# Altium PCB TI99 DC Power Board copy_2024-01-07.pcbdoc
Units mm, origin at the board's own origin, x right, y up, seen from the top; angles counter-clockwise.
Board outline 152.53 x 137.41 mm, 2 copper layers (Top Layer, Bottom Layer); 9 components, 10 nets, 53 pads, 1 vias.
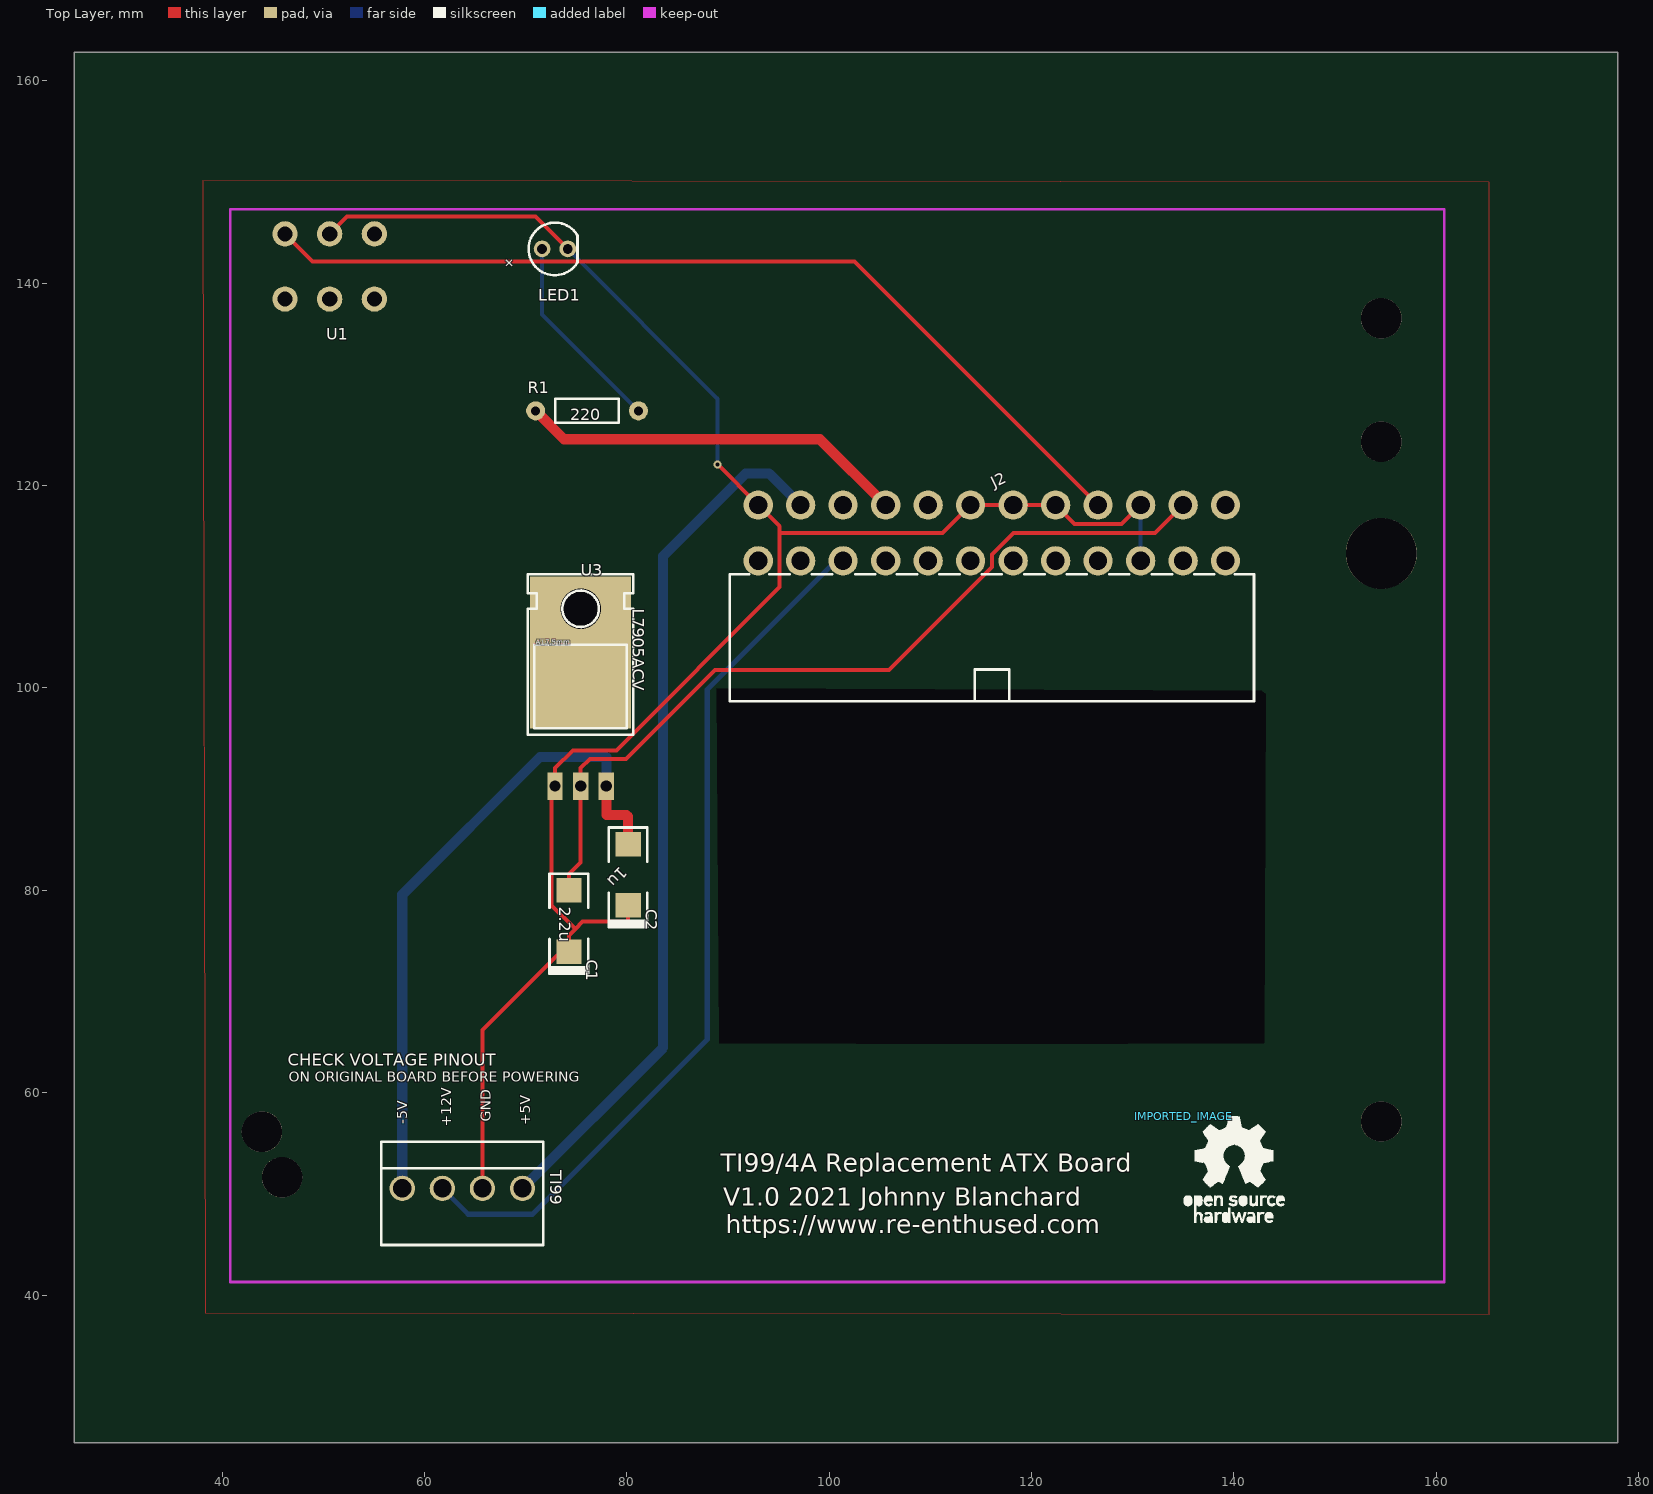
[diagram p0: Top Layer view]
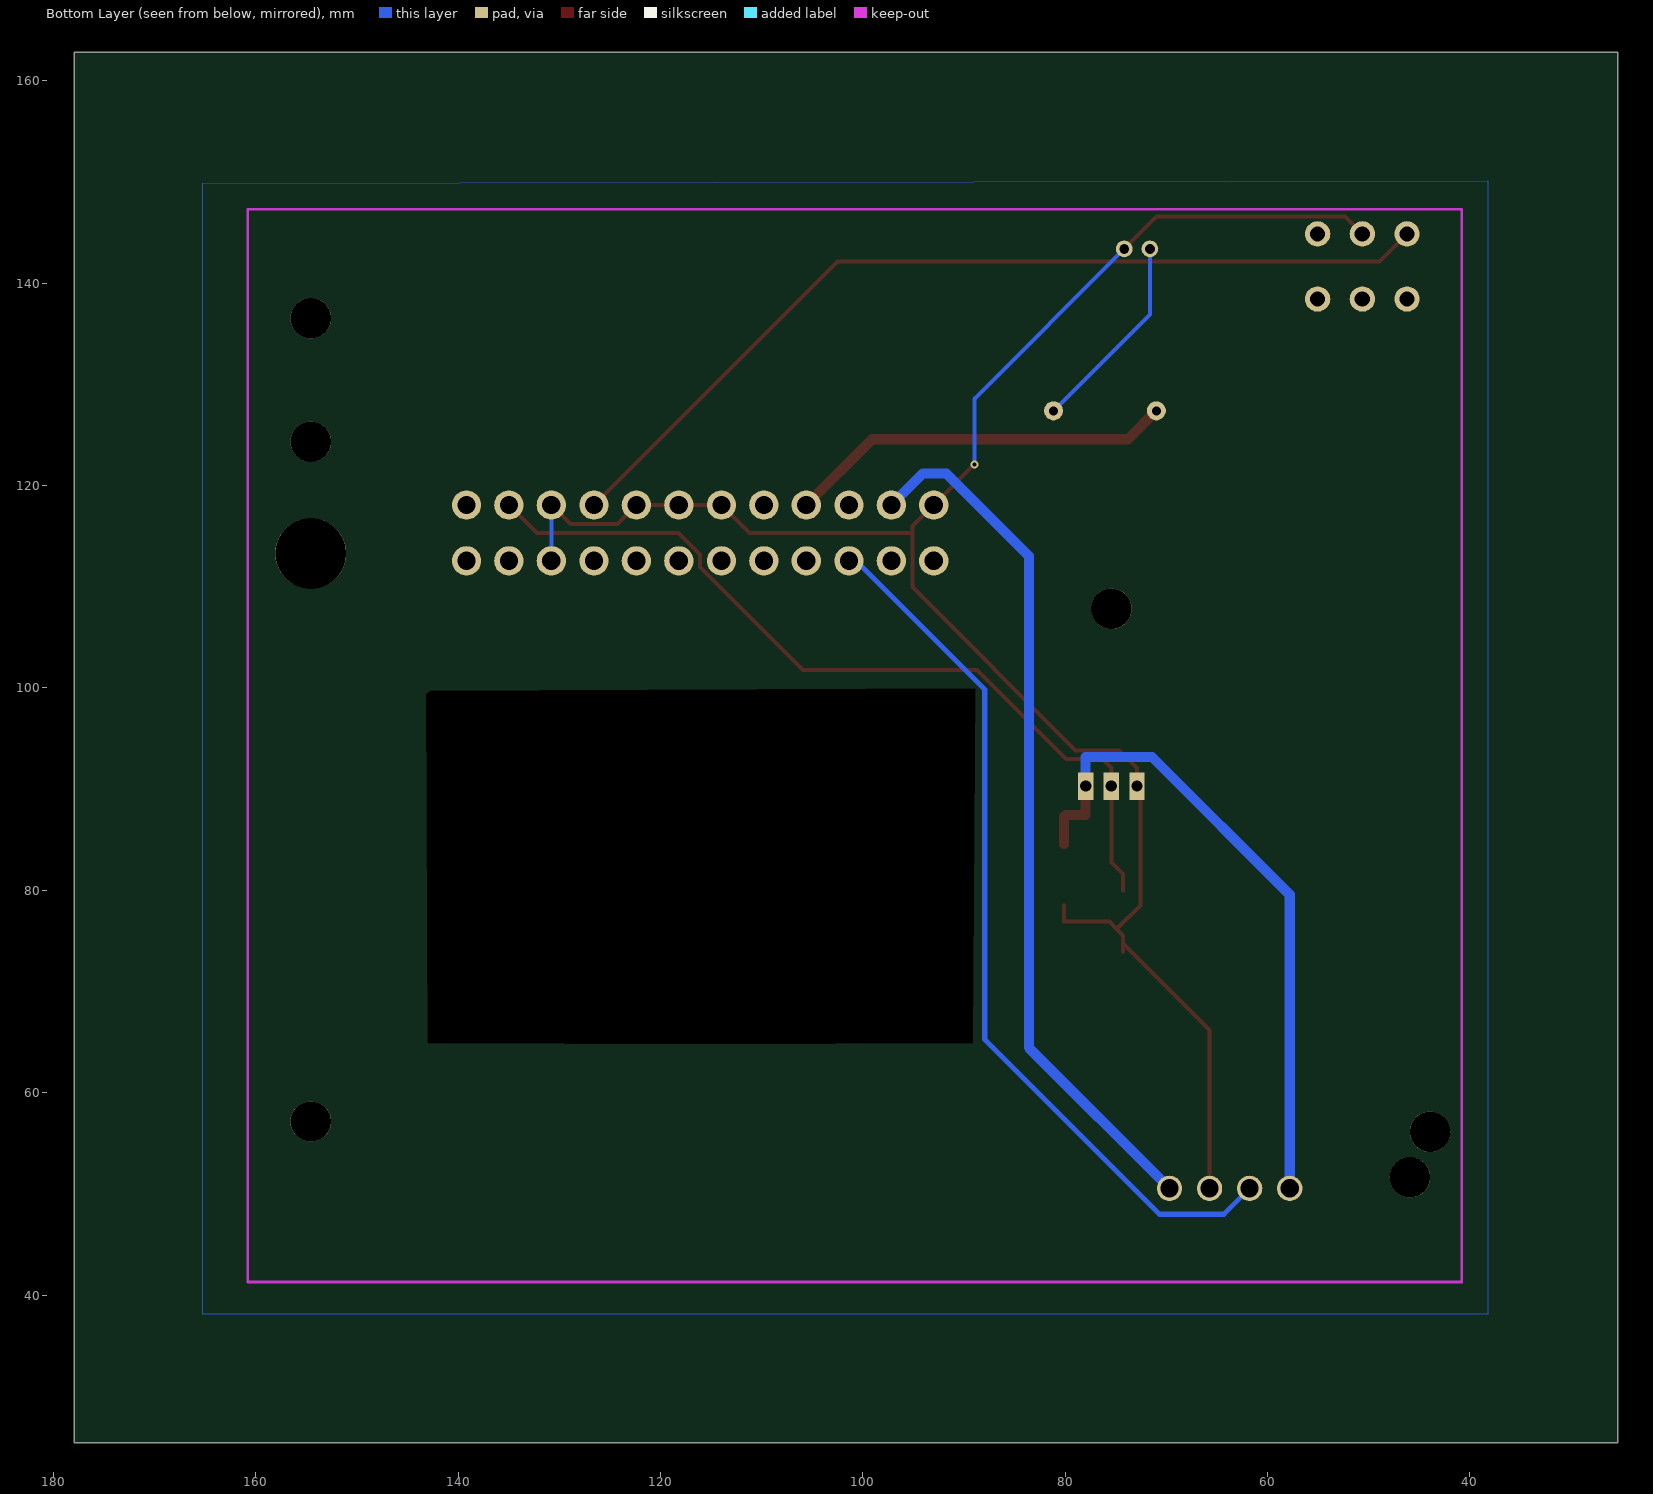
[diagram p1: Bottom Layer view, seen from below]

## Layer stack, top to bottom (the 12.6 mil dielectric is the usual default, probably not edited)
Top Layer: signal copper (thickness not stored)
Dielectric: dielectric 0.32, FR-4, Dk 4.8
Bottom Layer: signal copper (thickness not stored)

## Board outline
177.927,25.4 25.4,25.4 25.4,162.814 177.927,162.814
cut-out: 88.9,99.949 142.748,99.695 143.129,99.441 143.002,64.897 116.078,64.77 89.154,64.897

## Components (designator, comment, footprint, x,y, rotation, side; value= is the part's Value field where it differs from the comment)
C1 "2.2u" CASE-C_6032 74.295,76.962 r270 top
C2 "1u" CASE-C_6032 80.137,81.534 r270 top
IMPORTED_IMAGE "IMPORTED_IMAGE" IMPORTED_IMAGE 135.032,57.651 r0 top
J2 "ATX24RH" ATX24_RIGHT_ANGLE 116.078,115.316 r0 top
LED1 "LED-5MM" LED-5MM/2.54 72.898,143.383 r90 top
R1 "220" L_AXIAL-0.4 76.073,127.381 r0 top
TI99 "Header-Male-2.54_1x4" DIP-1X4P-3.96MM-SK 63.754,50.546 r0 top
U1 "Slide_Switch" SLIDE_SWITCH 52.197,138.176 r0 top
U3 "L7905ACV" TO220 75.438,90.297 r0 top

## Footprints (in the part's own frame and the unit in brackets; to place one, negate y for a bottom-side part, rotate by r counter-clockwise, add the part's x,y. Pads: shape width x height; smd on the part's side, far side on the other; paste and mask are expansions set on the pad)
ATX24_RIGHT_ANGLE [mil]
  round 114.2 hole 70.8 paste+0 mask+4: 1(909,-108.5) 2(744,-108.5) 3(579,-108.5) 4(413,-108.5) 5(248,-108.5) 6(83,-108.5) 7(-83,-108.5) 8(-248,-108.5) 9(-413,-108.5) 10(-579,-108.5) 11(-744,-108.5) 12(-909,-108.5) 13(909,108.5) 14(744,108.5) 15(579,108.5) 16(413,108.5) 17(248,108.5) 18(83,108.5) 19(-83,108.5) 20(-248,108.5) 21(-413,108.5) 22(-579,108.5) 23(-744,108.5) 24(-909,108.5)
  silkscreen extent -1020,-656 1020,-162
CASE-C_6032 [mil]
  rect 95.5x98.42 smd paste+0 mask+2: 1(119,0) 2(-119,0)
  silkscreen extent -184,-76 205,75
DIP-1X4P-3.96MM-SK [mm]
  round 2.5 hole 1.8 paste+0 mask+0.102: 1(-5.94,0) 2(-1.98,0) 3(1.98,0) 4(5.94,0)
  silkscreen extent -8,-5.6 8,4.6
IMPORTED_IMAGE [mm]
  silkscreen extent -0.01,-10.52 9.99,0
L_AXIAL-0.4 [mil]
  round 74 hole 35.4 paste+0 mask+4: 1(-200,0) 2(200,0)
  silkscreen extent -124,-47 124,47
LED-5MM/2.54 [mil]
  round 65 hole 38 paste+0 mask+4: 1(0,50) 2(0,-50)
  silkscreen extent -102,-88 102,102
SLIDE_SWITCH [mm]
  round 2.5 hole 1.5 paste+0 mask+0.102: 1(2.858,6.691) 2(-1.557,6.691) 3(-5.972,6.691) 4(2.858,0.254) 5(-1.557,0.254) 6(-5.972,0.254)
TO220 [mil]
  rect 59.7x107.5 hole 44 paste+0 mask+2: 1(-100,0) 2(0,0) 3(100,0)
  silkscreen extent -205,200 205,825

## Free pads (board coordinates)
  rect 10x15 smd paste+0 mask+0.102: 1(75.438,103.505)
  round 4 hole 4 unplated paste+0: ""(43.942,56.134) ""(45.942,51.634) ""(75.438,107.823) ""(154.559,57.15) ""(154.559,124.333) ""(154.559,136.525)
  round 7 hole 7 unplated paste+0: ""(154.559,113.284)

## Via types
v1: diameter 0.8, hole 0.4, Top Layer to Bottom Layer, tented both sides, 1 vias

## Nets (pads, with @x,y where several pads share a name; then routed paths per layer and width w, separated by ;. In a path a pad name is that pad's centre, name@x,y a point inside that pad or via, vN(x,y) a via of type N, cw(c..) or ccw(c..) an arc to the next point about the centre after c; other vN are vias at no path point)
12V: J2.10 TI99.2 | length 87.7
  Bottom Layer w0.5: TI99.2 64.334,47.986 70.68,47.986 87.95,65.256 87.95,99.844 100.667,112.56 J2.10
+5V1: J2.23 TI99.4 | length 86.5
  Bottom Layer w1: TI99.4 83.594,64.446 83.594,113.036 91.743,121.185 94.067,121.185 J2.23
+5V2: J2.21 R1.1 | length 38.5
  Top Layer w1: R1.1 73.796,124.578 99.081,124.578 J2.21
-5V: C2.2 TI99.1 U3.3 | length 65.5
  Top Layer w1: U3.3 77.978,87.431 79.976,87.431 80.137,87.27 C2.2
  Bottom Layer w1: TI99.1 57.814,79.562 71.415,93.163 77.978,93.163 U3.3
-12V: C1.2 J2.14 U3.2 | length 83.6
  Top Layer w0.4: C1.2 74.295,81.598 75.438,82.741 U3.2 75.438,92.063 76.362,92.987 79.901,92.987 88.703,101.789 105.927,101.789 116.078,111.94 116.078,113.176 118.218,115.316 132.22,115.316 J2.14
GND: C1.1 C2.1 J2.3 J2.15 J2.17 J2.18 J2.19 J2.24 LED1.2 TI99.3 U1.2 U3.1 | length 196.4
  Top Layer w0.4: U1.2 52.353,146.58 70.971,146.58 LED1.2 ; TI99.3 65.734,66.185 C1.1@74.295,74.746 ; U3.1 U3.1@72.898,91.18 ; C1.1 C1.1@74.295,74.746 ; C2.1 80.137,76.898 75.64,76.898 74.909,76.167 ; v1(88.976,122.066) 88.995,122.066 J2.24 95.085,115.976 95.085,115.316 ; J2.15 128.899,116.187 124.262,116.187 J2.17 J2.18 J2.19 111.214,115.316 95.085,115.316 ; U3.1@72.898,91.18 72.558,90.84 72.558,78.518 74.909,76.167 ; U3.1@72.898,91.18 72.898,92.063 74.669,93.834 78.968,93.834 95.085,109.951 95.085,115.316 ; C1.1@74.295,74.746 74.295,75.553 74.909,76.167
  Bottom Layer w0.4: LED1.2 88.976,128.575 v1(88.976,122.066) ; J2.3 J2.15
LED1_1: LED1.1 R1.2 | length 19.9
  Bottom Layer w0.4: LED1.1 71.628,136.906 R1.2
PS_ON: J2.16 U1.3 | length 91.4
  Top Layer w0.4: U1.3 48.936,142.156 102.484,142.156 J2.16
S$18: 
S$20: 
pads on no net: J2.1 J2.2 J2.4 J2.5 J2.6 J2.7 J2.8 J2.9 J2.11 J2.12 J2.13 J2.20 J2.22 U1.1 U1.4 U1.5 U1.6

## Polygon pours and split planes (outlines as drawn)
GND on Bottom Layer (solid): 38.227,150.114 38.227,38.1 165.227,38.1 165.227,149.86
GND on Top Layer (solid): 38.1,150.114 38.354,38.227 165.227,38.1 165.227,149.987

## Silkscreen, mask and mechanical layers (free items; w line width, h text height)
Top Overlay:
  text "+" at 68.48,142.721 h1 r225
  text "CHECK VOLTAGE PINOUT" at 46.482,62.646 h1.2
  text "ON ORIGINAL BOARD BEFORE POWERING" at 46.609,61.095 h1
  text "GND" at 66.578,57.135 h1 r90
  text "-5V" at 58.285,56.896 h1 r90
  text "+5V" at 70.477,56.769 h1 r90
  text "+12V" at 62.641,56.634 h1 r90
  text "TI99/4A Replacement ATX Board" at 89.281,52.186 h1.8
  text "V1.0 2021 Johnny Blanchard" at 89.535,48.846 h1.8
  text "https://www.re-enthused.com" at 89.789,46.128 h1.8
